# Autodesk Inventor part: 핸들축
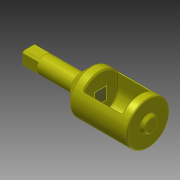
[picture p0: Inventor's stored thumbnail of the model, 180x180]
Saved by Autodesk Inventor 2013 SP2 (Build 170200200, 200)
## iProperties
Created: 2018-01
Part Number: 핸들축
Material: 강철, 연강
Document SubType Name: Modeling
Designer: mduedu
Density: 1 g/cm^3
Author: mduedu
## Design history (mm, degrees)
sketch "스케치1"
  geometry: L1 (0, 0)-(-109, 0); L2 (-46, -7.5)-(0, -7.5); L3 (0, -7.5)-(0, 0); L4 (-106, -19)-(-46, -19); L5 (-46, -19)-(-46, -7.5); L6 (-106, -7.5)-(-106, -19); L7 (-109, -5.768)-(-106, -7.5); L8 (-109, -5.768)-(-109, 0)
  constraints: 16 end point, 2 parallel, 1 horizontal, 1 vertical
  dimensions: "d8" = 15 diameter of L2 L1; "d43" = 46 distance between parallel lines of L3 L5; "d47" = 60 distance between parallel lines of L5 L6; "d63" = 3 distance between parallel lines of L6 L8; "d77" = 38 diameter of L4 L1; "d78" = 15 diameter of L6.start L1; "d79" = 30 deg angle of L1 L7
revolve "회전1" sketch "스케치1" stored, may be unused: angle "d9" = 90 deg
sketch "스케치4"
  geometry: L1 (-6, -6)-(-4.5, -6); L2 (6, -6)-(6, -4.5); L3 (6, 6)-(4.5, 6); L4 (-6, 6)-(-6, 4.5); L5 (-6, -6)-(6, 6); L6 (6, -6)-(-6, 6); L7 (-4.5, 6)-(-6, 6); L8 (-6, 4.5)-(-6, -4.5); L9 (-6, -4.5)-(-6, -6); L10 (-4.5, -6)-(4.5, -6); L11 (4.5, -6)-(6, -6); L12 (6, -4.5)-(6, 4.5); L13 (6, 4.5)-(6, 6); L14 (4.5, 6)-(-4.5, 6); C1 r 7.5 at (0, 0) reference; 2 further points
  constraints: 28 end point, 18 parallel, 9 perpendicular, 3 horizontal, 2 midpoint, 1 coincident, 11 other
  dimensions: "d20" = 12 distance of L4.start L3.start; "d21" = 12 distance of L3.start L2.start (= d20)
extrude "돌출2" cut sketch "스케치4" distance "d22" = 15; taper "d23" = 0 deg
chamfer "모따기2" distance "d24" = 1; stored, may be unused: second distance "d25" = 2, angle "d26" = 45 deg
sketch "스케치5"
  geometry: 2 further points
  constraints: 1 coincident
hole "구멍1" sketch "스케치5" at (5, 4.153) diameter "d27" = 2.459; stored, may be unused: countersink angle "d31" = 90 deg, drill point angle "d33" = 120 deg; dims "d28" = 6.9, "d29" = 4, "d30" = 2, "d32" = 8.4
node "작업 평면1"
sketch "스케치9"
  geometry: L1 (10, 4.153)-(10, 15.815); L2 (-20, 4.153)-(-20, 15.815); A1 r 15 centre (-5, 4.153) between (-20, 4.153) and (10, 4.153); A2 r 19 centre (-5, 4.153) between (10, 15.815) and (-20, 15.815) reference; 1 further point
  constraints: 4 end point, 4 point on circle, 2 tangent, 1 centre point, 1 coincident, 1 concentric, 1 parallel, 1 vertical
  dimensions: "d76" = 4 radial gap between concentric circles of A2 A1
extrude "돌출4" cut sketch "스케치9" distance "d73" = 34; taper "d74" = 0 deg
chamfer "모따기3" distance "d44" = 10; stored, may be unused: second distance "d45" = 2, angle "d46" = 45 deg
fillet "모깎기4" dims "d80" = 1
chamfer "모따기5" distance "d81" = 1; stored, may be unused: second distance "d82" = 2, angle "d83" = 45 deg
node "솔리드1"
other parameters: "d75" = -64
